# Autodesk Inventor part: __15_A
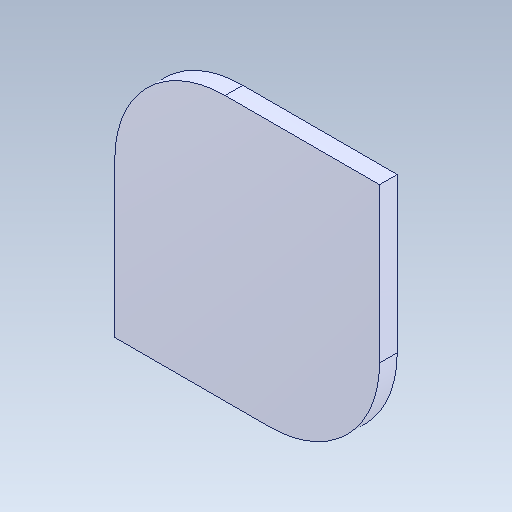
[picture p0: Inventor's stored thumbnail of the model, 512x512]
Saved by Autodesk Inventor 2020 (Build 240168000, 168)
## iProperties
Created: 2017-09
Part Number: __15_A
Material: Générique
Document SubType Name: Modeling
Designer: bruno
Density: 1 g/cm^3
Appearance: Par défaut
Author: bruno
Sending System: SolidWorks 2016
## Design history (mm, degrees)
feature "Importée1"
node "Solide1"
